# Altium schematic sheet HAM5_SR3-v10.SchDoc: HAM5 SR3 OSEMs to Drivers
size C; Engineer: L. Sanchez; Organization: LIGO Laboratory; Address1: California Institute of Technology; Address2: Massachusetts Institute of Technology; DocumentNumber: D1002740; Revision: v10; SheetNumber: 1; SheetTotal: 8
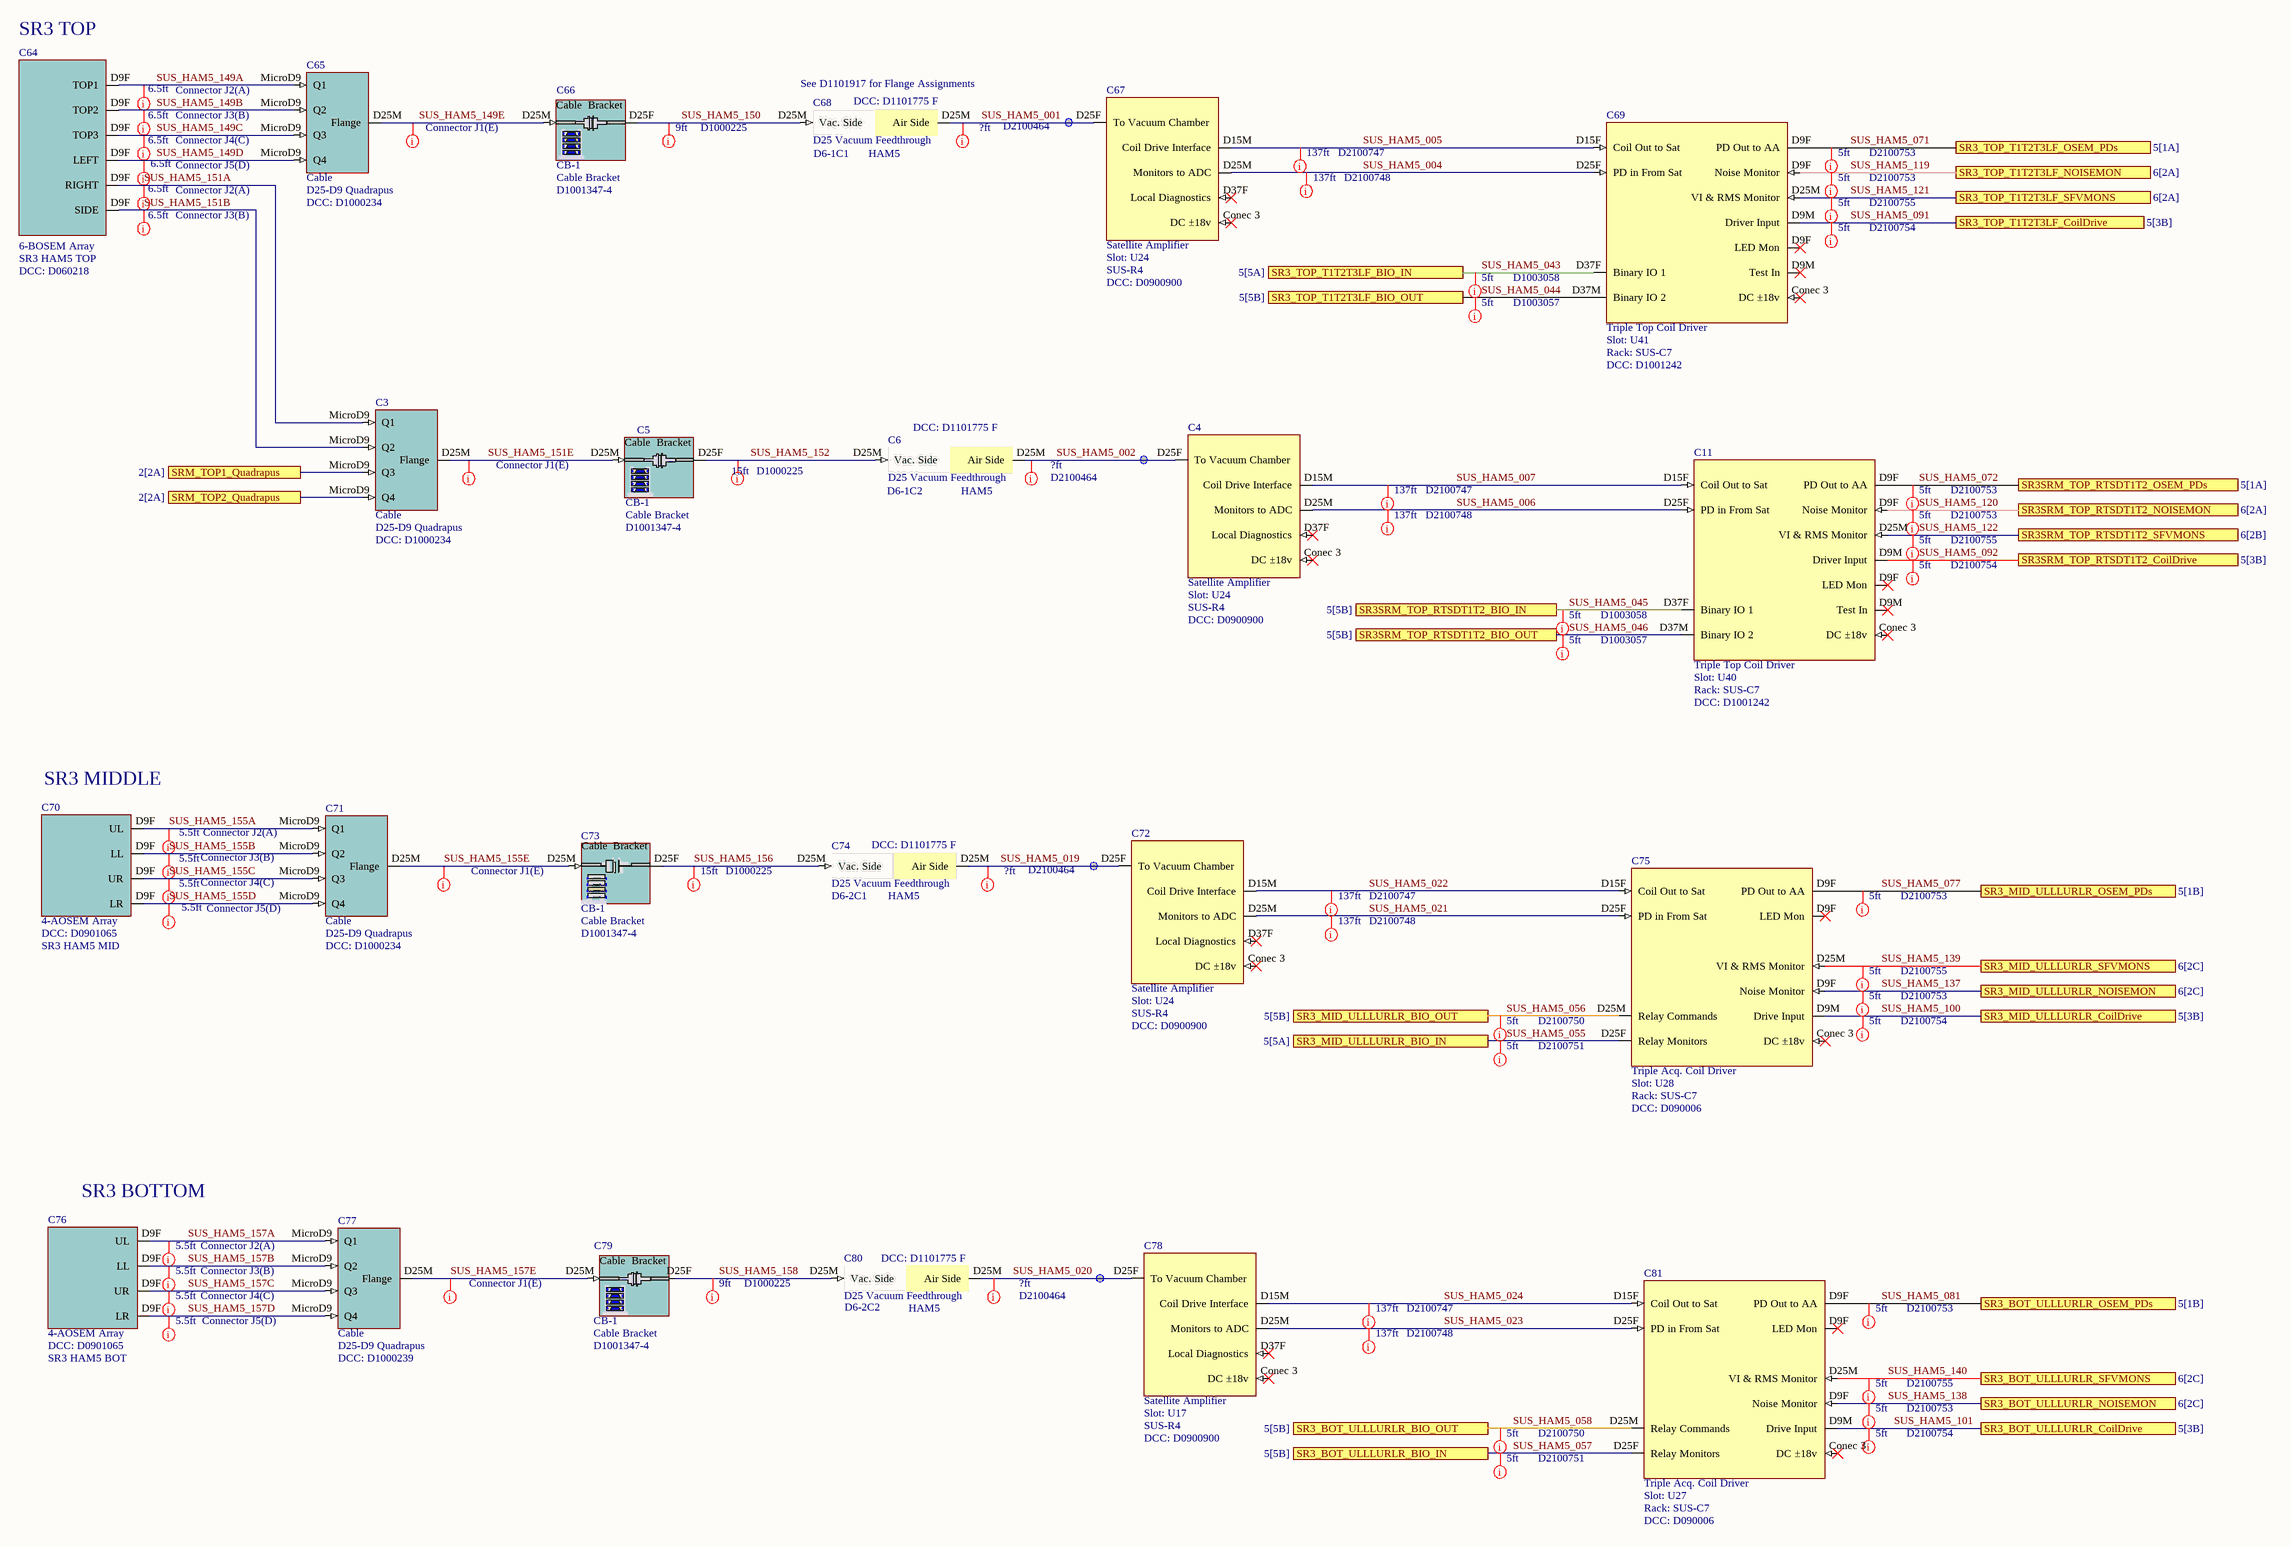
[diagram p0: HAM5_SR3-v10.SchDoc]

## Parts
C3  Cable  value D25-D9 Quadrapus  DCC: D1000234
C4  Satellite Amplifier  Slot: U24  Rack: SUS-R4  DCC: D0900900
C5  Slot: CB-1  DCC: D1001347-4  (hidden comment: Cable Bracket)
C6  D25 Vacuum Feedthrough  DCC: D1101775 F  Feedthrough: D6-1C2  Chamber: HAM5
C11  Triple Top Coil Driver  Slot: U40  Rack: SUS-C7  DCC: D1001242
C64  6-BOSEM Array  Parameter 1: SR3 HAM5 TOP  DCC: D060218
C65  Cable  value D25-D9 Quadrapus  DCC: D1000234
C66  Slot: CB-1  DCC: D1001347-4  (hidden comment: Cable Bracket)
C67  Satellite Amplifier  Slot: U24  Rack: SUS-R4  DCC: D0900900
C68  D25 Vacuum Feedthrough  DCC: D1101775 F  Feedthrough: D6-1C1  Chamber: HAM5
C69  Triple Top Coil Driver  Slot: U41  Rack: SUS-C7  DCC: D1001242
C70  4-AOSEM Array  DCC: D0901065  Parameter: SR3 HAM5 MID
C71  Cable  value D25-D9 Quadrapus  DCC: D1000234
C72  Satellite Amplifier  Slot: U24  Rack: SUS-R4  DCC: D0900900
C73  Slot: CB-1  DCC: D1001347-4  (hidden comment: Cable Bracket)
C74  D25 Vacuum Feedthrough  DCC: D1101775 F  Feedthrough: D6-2C1  Chamber: HAM5
C75  Triple Acq. Coil Driver  Slot: U28  Rack: SUS-C7  DCC: D090006
C76  4-AOSEM Array  DCC: D0901065  Parameter: SR3 HAM5 BOT
C77  Cable  value D25-D9 Quadrapus  DCC: D1000239
C78  Satellite Amplifier  Slot: U17  Rack: SUS-R4  DCC: D0900900
C79  Slot: CB-1  DCC: D1001347-4  (hidden comment: Cable Bracket)
C80  D25 Vacuum Feedthrough  DCC: D1101775 F  Feedthrough: D6-2C2  Chamber: HAM5
C81  Triple Acq. Coil Driver  Slot: U27  Rack: SUS-C7  DCC: D090006

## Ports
SR3_BOT_ULLLURLR_BIO_IN (see 5[5B]), SR3_BOT_ULLLURLR_BIO_OUT (see 5[5B]), SR3_BOT_ULLLURLR_CoilDrive (see 5[3B]), SR3_BOT_ULLLURLR_NOISEMON (see 6[2C]), SR3_BOT_ULLLURLR_OSEM_PDs (see 5[1B]), SR3_BOT_ULLLURLR_SFVMONS (see 6[2C]), SR3_MID_ULLLURLR_BIO_IN (see 5[5A]), SR3_MID_ULLLURLR_BIO_OUT (see 5[5B]), SR3_MID_ULLLURLR_CoilDrive (see 5[3B]), SR3_MID_ULLLURLR_NOISEMON (see 6[2C]), SR3_MID_ULLLURLR_OSEM_PDs (see 5[1B]), SR3_MID_ULLLURLR_SFVMONS (see 6[2C]), SR3_TOP_T1T2T3LF_BIO_IN (see 5[5A]), SR3_TOP_T1T2T3LF_BIO_OUT (see 5[5B]), SR3_TOP_T1T2T3LF_CoilDrive (see 5[3B]), SR3_TOP_T1T2T3LF_NOISEMON (see 6[2A]), SR3_TOP_T1T2T3LF_OSEM_PDs (see 5[1A]), SR3_TOP_T1T2T3LF_SFVMONS (see 6[2A]), SR3SRM_TOP_RTSDT1T2_BIO_IN (see 5[5B]), SR3SRM_TOP_RTSDT1T2_BIO_OUT (see 5[5B]), SR3SRM_TOP_RTSDT1T2_CoilDrive (see 5[3B]), SR3SRM_TOP_RTSDT1T2_NOISEMON (see 6[2A]), SR3SRM_TOP_RTSDT1T2_OSEM_PDs (see 5[1A]), SR3SRM_TOP_RTSDT1T2_SFVMONS (see 6[2B]), SRM_TOP1_Quadrapus (see 2[2A]), SRM_TOP2_Quadrapus (see 2[2A])

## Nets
SRM_TOP1_Quadrapus: C3.MicroD9(Q3) ; port SRM_TOP1_Quadrapus
SRM_TOP2_Quadrapus: C3.MicroD9(Q4) ; port SRM_TOP2_Quadrapus
SUS_HAM5_001: C67.D25F(To_Vacuum_Chamber) C68.D25M(Air_Side)
SUS_HAM5_002: C4.D25F(To_Vacuum_Chamber) C6.D25M(Air_Side)
SUS_HAM5_004: C67.D25M(Monitors_to_ADC) C69.D25F(PD_in_From_Sat)
SUS_HAM5_005: C67.D15M(Coil_Drive_Interface) C69.D15F(Coil_Out_to_Sat)
SUS_HAM5_006: C4.D25M(Monitors_to_ADC) C11.D25F(PD_in_From_Sat)
SUS_HAM5_007: C4.D15M(Coil_Drive_Interface) C11.D15F(Coil_Out_to_Sat)
SUS_HAM5_019: C72.D25F(To_Vacuum_Chamber) C74.D25M(Air_Side)
SUS_HAM5_020: C78.D25F(To_Vacuum_Chamber) C80.D25M(Air_Side)
SUS_HAM5_021: C72.D25M(Monitors_to_ADC) C75.D25F(PD_in_From_Sat)
SUS_HAM5_022: C72.D15M(Coil_Drive_Interface) C75.D15F(Coil_Out_to_Sat)
SUS_HAM5_023: C78.D25M(Monitors_to_ADC) C81.D25F(PD_in_From_Sat)
SUS_HAM5_024: C78.D15M(Coil_Drive_Interface) C81.D15F(Coil_Out_to_Sat)
SUS_HAM5_043: C69.D37F(Binary_IO_1) ; port SR3_TOP_T1T2T3LF_BIO_IN
SUS_HAM5_044: C69.D37M(Binary_IO_2) ; port SR3_TOP_T1T2T3LF_BIO_OUT
SUS_HAM5_045: C11.D37F(Binary_IO_1) ; port SR3SRM_TOP_RTSDT1T2_BIO_IN
SUS_HAM5_046: C11.D37M(Binary_IO_2) ; port SR3SRM_TOP_RTSDT1T2_BIO_OUT
SUS_HAM5_055: C75.D25F(Relay_Monitors) ; port SR3_MID_ULLLURLR_BIO_IN
SUS_HAM5_056: C75.D25M(Relay_Commands) ; port SR3_MID_ULLLURLR_BIO_OUT
SUS_HAM5_057: C81.D25F(Relay_Monitors) ; port SR3_BOT_ULLLURLR_BIO_IN
SUS_HAM5_058: C81.D25M(Relay_Commands) ; port SR3_BOT_ULLLURLR_BIO_OUT
SUS_HAM5_071: C69.D9F(PD_Out_to_AA) ; port SR3_TOP_T1T2T3LF_OSEM_PDs
SUS_HAM5_072: C11.D9F(PD_Out_to_AA) ; port SR3SRM_TOP_RTSDT1T2_OSEM_PDs
SUS_HAM5_077: C75.D9F(PD_Out_to_AA) ; port SR3_MID_ULLLURLR_OSEM_PDs
SUS_HAM5_081: C81.D9F(PD_Out_to_AA) ; port SR3_BOT_ULLLURLR_OSEM_PDs
SUS_HAM5_091: C69.D9M(Test_In) ; port SR3_TOP_T1T2T3LF_CoilDrive
SUS_HAM5_092: C11.D9M(Test_In) ; port SR3SRM_TOP_RTSDT1T2_CoilDrive
SUS_HAM5_100: C75.D9M(Drive_Input) ; port SR3_MID_ULLLURLR_CoilDrive
SUS_HAM5_101: C81.D9M(Drive_Input) ; port SR3_BOT_ULLLURLR_CoilDrive
SUS_HAM5_119: C69.D9F(Noise_Monitor) ; port SR3_TOP_T1T2T3LF_NOISEMON
SUS_HAM5_120: C11.D9F(Noise_Monitor) ; port SR3SRM_TOP_RTSDT1T2_NOISEMON
SUS_HAM5_121: C69.D25M(VI_&_RMS_Monitor) ; port SR3_TOP_T1T2T3LF_SFVMONS
SUS_HAM5_122: C11.D25M(VI_&_RMS_Monitor) ; port SR3SRM_TOP_RTSDT1T2_SFVMONS
SUS_HAM5_137: C75.D9F(Noise_Monitor) ; port SR3_MID_ULLLURLR_NOISEMON
SUS_HAM5_138: C81.D9F(Noise_Monitor) ; port SR3_BOT_ULLLURLR_NOISEMON
SUS_HAM5_139: C75.D25M(VI_&_RMS_Monitor) ; port SR3_MID_ULLLURLR_SFVMONS
SUS_HAM5_140: C81.D25M(VI_&_RMS_Monitor) ; port SR3_BOT_ULLLURLR_SFVMONS
SUS_HAM5_149A: C64.D9F(TOP1) C65.MicroD9(Q1)
SUS_HAM5_149B: C64.D9F(TOP2) C65.MicroD9(Q2)
SUS_HAM5_149C: C64.D9F(TOP3) C65.MicroD9(Q3)
SUS_HAM5_149D: C64.D9F(LEFT) C65.MicroD9(Q4)
SUS_HAM5_149E: C65.D25M(Flange) C66.D25M
SUS_HAM5_150: C66.D25F C68.D25M(Vac._Side)
SUS_HAM5_151A: C3.MicroD9(Q1) C64.D9F(RIGHT)
SUS_HAM5_151B: C3.MicroD9(Q2) C64.D9F(SIDE)
SUS_HAM5_151E: C3.D25M(Flange) C5.D25M
SUS_HAM5_152: C5.D25F C6.D25M(Vac._Side)
SUS_HAM5_155A: C70.D9F(UL) C71.MicroD9(Q1)
SUS_HAM5_155B: C70.D9F(LL) C71.MicroD9(Q2)
SUS_HAM5_155C: C70.D9F(UR) C71.MicroD9(Q3)
SUS_HAM5_155D: C70.D9F(LR) C71.MicroD9(Q4)
SUS_HAM5_155E: C71.D25M(Flange) C73.D25M
SUS_HAM5_156: C73.D25F C74.D25M(Vac._Side)
SUS_HAM5_157A: C76.D9F(UL) C77.MicroD9(Q1)
SUS_HAM5_157B: C76.D9F(LL) C77.MicroD9(Q2)
SUS_HAM5_157C: C76.D9F(UR) C77.MicroD9(Q3)
SUS_HAM5_157D: C76.D9F(LR) C77.MicroD9(Q4)
SUS_HAM5_157E: C77.D25M(Flange) C79.D25M
SUS_HAM5_158: C79.D25F C80.D25M(Vac._Side)

Not connected (* = marked no-connect by the designer): C4 Conec 3(DC_±18v)* D37F(Local_Diagnostics)*; C11 Conec 3(DC_±18v)*; C67 Conec 3(DC_±18v)* D37F(Local_Diagnostics)*; C69 Conec 3(DC_±18v)*; C72 Conec 3(DC_±18v)* D37F(Local_Diagnostics)*; C75 Conec 3(DC_±18v)*; C78 Conec 3(DC_±18v)* D37F(Local_Diagnostics)*; C81 Conec 3(DC_±18v)*

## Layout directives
Length: 6.5ft; DCC: Connector J1(E): SUS_HAM5_149E, SUS_HAM5_151E
Length: 15ft; DCC: D1000225: SUS_HAM5_152, SUS_HAM5_156
Length: ?ft; DCC: D2100464: SUS_HAM5_001, SUS_HAM5_002, SUS_HAM5_019, SUS_HAM5_020
Length: 6.5ft; DCC: Connector J2(A): SUS_HAM5_149A, SUS_HAM5_151A
Length: 6.5ft; DCC: Connector J3(B): SUS_HAM5_149B, SUS_HAM5_151B
Length: 9ft; DCC: D1000225: SUS_HAM5_150, SUS_HAM5_158
Length: 6.5ft; DCC: Connector J4(C): SUS_HAM5_149C
Length: 6.5ft; DCC: Connector J5(D): SUS_HAM5_149D
Length: 5ft; DCC: Connector J1(E): SUS_HAM5_157E
Length: 5.5ft; DCC: Connector J1(E): SUS_HAM5_155E
Length: 5.5ft; DCC: Connector J2(A): SUS_HAM5_155A, SUS_HAM5_157A
Length: 5.5ft; DCC: Connector J3(B): SUS_HAM5_155B, SUS_HAM5_157B
Length: 5.5ft; DCC: Connector J4(C): SUS_HAM5_155C, SUS_HAM5_157C
Length: 5.5ft; DCC: Connector J5(D): SUS_HAM5_155D, SUS_HAM5_157D
Length: 137ft; DCC: D2100748: SUS_HAM5_004, SUS_HAM5_006, SUS_HAM5_021, SUS_HAM5_023
Length: 137ft; DCC: D2100747: SUS_HAM5_005, SUS_HAM5_007, SUS_HAM5_022, SUS_HAM5_024
Length: 5ft; DCC: D1003058: SUS_HAM5_043, SUS_HAM5_045
Length: 5ft; DCC: D1003057: SUS_HAM5_044, SUS_HAM5_046
Length: 5ft; DCC: D2100754: SUS_HAM5_091, SUS_HAM5_092, SUS_HAM5_100, SUS_HAM5_101
Length: 5ft; DCC: D2100755: SUS_HAM5_121, SUS_HAM5_122, SUS_HAM5_139, SUS_HAM5_140
Length: 5ft; DCC: D2100753: SUS_HAM5_071, SUS_HAM5_072, SUS_HAM5_077, SUS_HAM5_081, SUS_HAM5_119, SUS_HAM5_120, SUS_HAM5_137, SUS_HAM5_138
Length: 5ft; DCC: D2100751: SUS_HAM5_055, SUS_HAM5_057
Length: 5ft; DCC: D2100750: SUS_HAM5_056, SUS_HAM5_058

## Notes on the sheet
- (near C64) SR3 TOP
- (near C68) See D1101917 for Flange Assignments
- (near C70) SR3 MIDDLE
- (near C76) SR3 BOTTOM

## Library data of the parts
C3 C65 C71 C77 = Flange: Rack: SUS-R?; Serial: Sxxxxxxx; Slot: U?; System: SUS
C4 C67 C72 C78 = Satellite Amplifier: System: SUS; Serial: Sxxxxxxx
C5 = Cable Bracket 4 1-4: Rack: SUS-R?; Serial: Sxxxxxxx; System: SUS
C6 C68 C74 C80 = VacFeedD25: Serial: Sxxxxxxx; System: ISC; Rack: R?; Slot: U?
C11 C69 = Triple Top CD: System: SUS; Serial: Sxxxxxxx
C64 = 6-BOSEM Array HAM: Serial: Sxxxxxxx; System: SUS; Slot: U?; Rack: SUS-R?
C66 = Cable Bracket 3 1-4: Rack: SUS-R?; Serial: Sxxxxxxx; System: SUS
C70 C76 = 4-BOSEM Array: Rack: SUS-R?; Serial: Sxxxxxxx; Slot: U?; System: SUS
C73 = Cable Bracket 2 1-4: Rack: SUS-R?; Serial: Sxxxxxxx; System: SUS
C75 C81 = Triple Acquisition Coil Driver: System: SUS; Serial: Sxxxxxxx
C79 = Cable Bracket 1 1-4: Rack: SUS-R?; Serial: Sxxxxxxx; System: SUS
